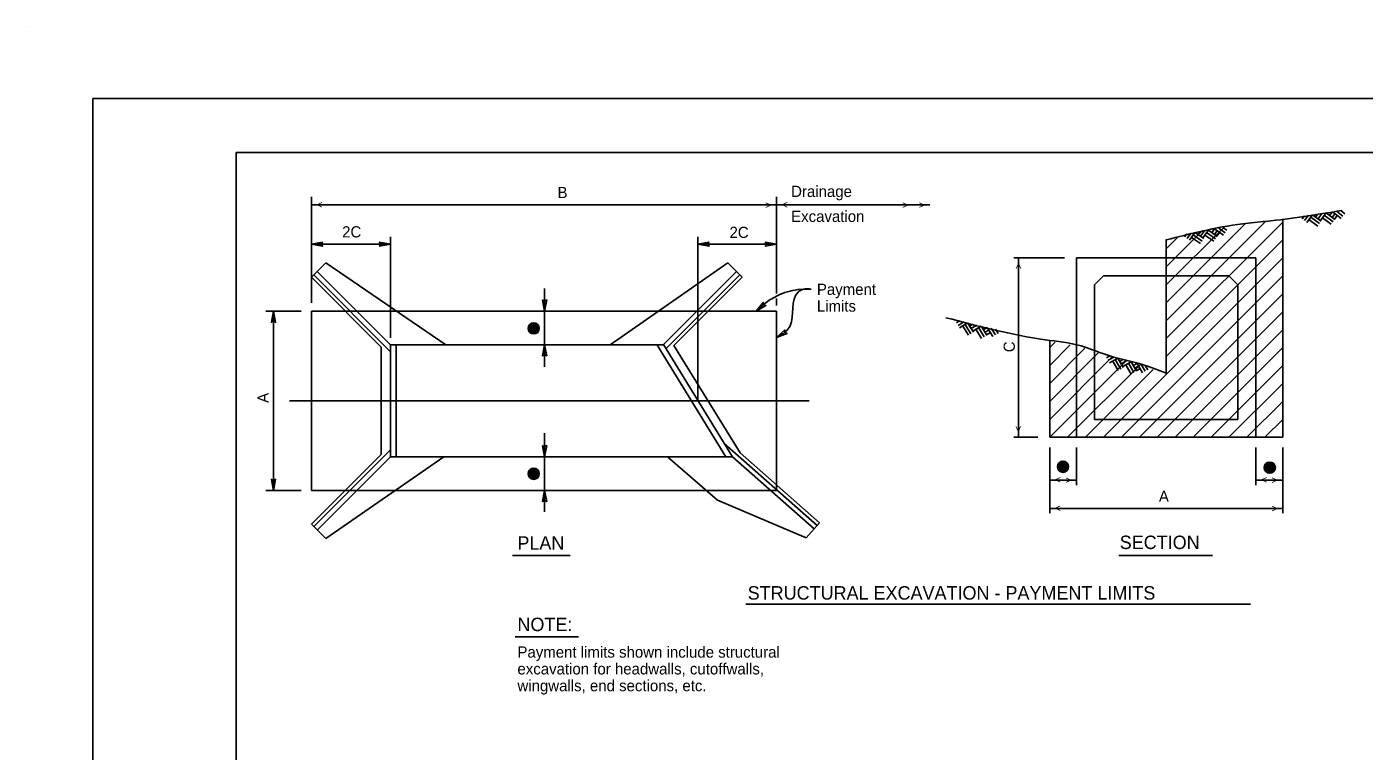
# Model space of a CAD drawing. Extents: x -0.08 to 2.83, y -0.03 to 1.92.
# Drawn here: x -0.077 to 1.477, y 1.075 to 1.917 of the extents above; entities that cross this region are included whole.
import ezdxf

# ---------------------------------------------------------------- set-up
doc = ezdxf.new("R2010")
doc.units = 0
for name, color, linetype in [('21', 7, 'Continuous'), ('50', 7, 'Continuous'), ('54', 7, 'Continuous'), ('55', 7, 'Continuous'), ('57', 7, 'Continuous'), ('63', 7, 'Continuous')]:
    doc.layers.add(name, color=color, linetype=linetype)

msp = doc.modelspace()

# ---------------------------------------------------------------- linework, layer by layer
at = {"layer": '21'}
msp.add_line((-0.0767, 1.9167), (-0.0767, 1.9167), dxfattribs=at)
at = {"layer": '50'}
for p, q in [((1.4052, 1.6937), (1.4078, 1.6971)), ((1.408, 1.6916), (1.4126, 1.6978)), ((1.4107, 1.6895), (1.4174, 1.6984)), ((1.4153, 1.6956), (1.4254, 1.688)), ((1.4174, 1.6984), (1.4275, 1.6908)), ((1.4209, 1.6958), (1.4235, 1.6992)), ((1.4237, 1.6937), (1.4283, 1.6999)), ((1.4264, 1.6916), (1.4331, 1.7005)), ((1.4289, 1.6949), (1.439, 1.6874)), ((1.431, 1.6977), (1.4411, 1.6901)), ((1.4331, 1.7005), (1.4432, 1.6929)), ((1.4372, 1.6974), (1.4404, 1.7017)), ((1.44, 1.6953), (1.4432, 1.6996)), ((1.4404, 1.7017), (1.4505, 1.6941)), ((1.4428, 1.6932), (1.446, 1.6975)), ((1.4453, 1.7024), (1.4526, 1.6968)), ((1.4501, 1.7031), (1.4547, 1.6996)), ((1.2843, 1.6754), (1.2867, 1.6789)), ((1.2871, 1.6734), (1.2916, 1.6797)), ((1.29, 1.6714), (1.2963, 1.6805)), ((1.2963, 1.6805), (1.3066, 1.6732)), ((1.3005, 1.6775), (1.3036, 1.6819)), ((1.3034, 1.6755), (1.3065, 1.6799)), ((1.3036, 1.6819), (1.3139, 1.6747)), ((1.3084, 1.6828), (1.3159, 1.6775)), ((1.3132, 1.6837), (1.3179, 1.6804)), ((1.4132, 1.6928), (1.4233, 1.6852)), ((1.2687, 1.6727), (1.2711, 1.6762)), ((1.2715, 1.6707), (1.276, 1.6771)), ((1.2744, 1.6687), (1.2807, 1.6778)), ((1.2767, 1.6721), (1.2871, 1.6649)), ((1.2787, 1.675), (1.2891, 1.6677)), ((1.2807, 1.6778), (1.291, 1.6706)), ((1.2923, 1.6748), (1.3027, 1.6676)), ((1.2943, 1.6776), (1.3047, 1.6704)), ((1.3062, 1.6735), (1.3093, 1.6779)), ((1.1432, 1.6482), (1.3515, 1.6482)), ((1.1432, 1.4399), (1.1432, 1.6482)), ((1.3515, 1.4399), (1.3515, 1.6482)), ((0.2541, 1.6257), (0.2708, 1.6424)), ((0.2609, 1.6326), (0.3461, 1.5474)), ((0.4101, 1.5474), (0.2708, 1.6424)), ((0.6012, 1.5474), (0.7379, 1.6424)), ((0.663, 1.5475), (0.7479, 1.6324)), ((0.7546, 1.6257), (0.7379, 1.6424)), ((0.2541, 1.6257), (0.3351, 1.5447)), ((0.2569, 1.6285), (0.3461, 1.5392)), ((0.6662, 1.5429), (0.7518, 1.6285)), ((0.6753, 1.5465), (0.7546, 1.6257)), ((1.164, 1.617), (1.1744, 1.6274)), ((1.164, 1.4607), (1.164, 1.617)), ((1.1744, 1.6274), (1.3202, 1.6274)), ((1.3307, 1.617), (1.3202, 1.6274)), ((1.3307, 1.4607), (1.3307, 1.617)), ((1.0036, 1.5728), (1.0072, 1.5751)), ((1.0054, 1.5698), (1.012, 1.574)), ((1.0073, 1.5669), (1.0166, 1.5728)), ((1.0137, 1.5709), (1.0204, 1.5602)), ((1.0166, 1.5728), (1.0233, 1.5621)), ((1.019, 1.5692), (1.0226, 1.5714)), ((1.0208, 1.5662), (1.0274, 1.5703)), ((1.0108, 1.5691), (1.0174, 1.5584)), ((1.0227, 1.5633), (1.0321, 1.5691)), ((1.0262, 1.5655), (1.0328, 1.5548)), ((1.0291, 1.5673), (1.0358, 1.5566)), ((1.0321, 1.5691), (1.0387, 1.5585)), ((1.0348, 1.5648), (1.0393, 1.5676)), ((1.0366, 1.5618), (1.0412, 1.5647)), ((1.0385, 1.5589), (1.043, 1.5617)), ((1.0393, 1.5676), (1.046, 1.5569)), ((1.0441, 1.5665), (1.0489, 1.5588)), ((1.0488, 1.5655), (1.0519, 1.5606)), ((0.3351, 1.4199), (0.3351, 1.5447)), ((0.3461, 1.4172), (0.3461, 1.5474)), ((0.3461, 1.5474), (0.663, 1.5474)), ((0.3526, 1.4172), (0.3526, 1.5474)), ((0.7356, 1.4174), (0.6553, 1.5475)), ((0.7433, 1.4173), (0.663, 1.5475)), ((0.7523, 1.4217), (0.6753, 1.5465)), ((1.178, 1.5323), (1.1817, 1.5344)), ((1.1798, 1.5293), (1.1865, 1.5331)), ((1.1815, 1.5263), (1.1911, 1.5318)), ((1.1851, 1.5283), (1.1914, 1.5174)), ((1.1881, 1.5301), (1.1944, 1.5191)), ((1.1911, 1.5318), (1.1974, 1.5209)), ((1.1933, 1.5281), (1.197, 1.5302)), ((1.195, 1.5251), (1.2017, 1.529)), ((1.1968, 1.5221), (1.2064, 1.5276)), ((1.2004, 1.5242), (1.2067, 1.5132)), ((1.2034, 1.5259), (1.2097, 1.515)), ((1.2064, 1.5276), (1.2127, 1.5167)), ((1.2089, 1.5232), (1.2136, 1.5258)), ((1.2136, 1.5258), (1.2199, 1.5149)), ((1.2183, 1.5246), (1.2229, 1.5167)), ((1.223, 1.5234), (1.2259, 1.5184)), ((1.2107, 1.5201), (1.2153, 1.5228)), ((1.2124, 1.5171), (1.2171, 1.5198)), ((1.164, 1.4607), (1.3307, 1.4607)), ((0.7337, 1.4328), (0.8418, 1.3376)), ((1.1432, 1.4399), (1.3515, 1.4399)), ((0.2541, 1.3389), (0.3351, 1.4199)), ((0.2569, 1.3362), (0.3461, 1.4254)), ((0.2613, 1.3324), (0.3461, 1.4172)), ((0.4078, 1.4172), (0.2708, 1.3223)), ((0.3461, 1.4172), (0.7433, 1.4172)), ((0.7258, 1.3669), (0.6679, 1.4172)), ((0.7433, 1.4173), (0.8383, 1.3336)), ((0.7523, 1.4217), (0.8445, 1.3406)), ((0.829, 1.323), (0.7258, 1.3669)), ((0.2541, 1.3389), (0.2708, 1.3223)), ((0.829, 1.323), (0.8445, 1.3406))]:
    msp.add_line(p, q, dxfattribs=at)
at = {"layer": '54'}
for points in [[(0.2541, 1.6641), (0.2671, 1.6618), (0.2656, 1.6641), (0.2669, 1.6665)], [(0.3461, 1.6641), (0.3331, 1.6665), (0.3346, 1.6641), (0.3333, 1.6617)], [(0.7032, 1.6641), (0.7162, 1.6618), (0.7147, 1.6641), (0.716, 1.6665)], [(0.7944, 1.6641), (0.7815, 1.6665), (0.783, 1.6641), (0.7816, 1.6617)], [(0.2101, 1.5865), (0.2077, 1.5735), (0.2101, 1.575), (0.2125, 1.5736)], [(0.5251, 1.5865), (0.5275, 1.5995), (0.5251, 1.598), (0.5227, 1.5993)], [(0.7707, 1.5865), (0.7822, 1.593), (0.7795, 1.5938), (0.779, 1.5965)], [(0.7944, 1.5558), (0.8068, 1.5606), (0.8042, 1.5618), (0.8042, 1.5646)], [(0.5251, 1.5474), (0.5227, 1.5344), (0.5251, 1.5359), (0.5275, 1.5346)], [(0.5251, 1.4172), (0.5275, 1.4302), (0.5251, 1.4287), (0.5227, 1.43)], [(0.2101, 1.3781), (0.2125, 1.3911), (0.2101, 1.3896), (0.2077, 1.391)], [(0.5251, 1.3781), (0.5227, 1.3652), (0.5251, 1.3667), (0.5275, 1.3653)]]:
    msp.add_lwpolyline(points, close=True, dxfattribs=at)
at = {"layer": '55'}
for p, q in [((0.2541, 1.5962), (0.2541, 1.7192)), ((0.2541, 1.7098), (0.7944, 1.7098)), ((0.7944, 1.6069), (0.7944, 1.7192)), ((0.7944, 1.7098), (0.9728, 1.7098)), ((1.2473, 1.5753), (1.3623, 1.6903)), ((1.2473, 1.5545), (1.3827, 1.6899)), ((1.2473, 1.5961), (1.3393, 1.6881)), ((1.2473, 1.617), (1.3153, 1.6849)), ((1.2473, 1.6378), (1.2896, 1.6801)), ((1.3827, 1.4399), (1.3827, 1.6935)), ((0.2541, 1.6641), (0.3461, 1.6641)), ((0.3461, 1.5555), (0.3461, 1.6729)), ((0.7032, 1.4824), (0.7032, 1.6729)), ((0.7032, 1.6641), (0.7944, 1.6641)), ((1.2473, 1.6586), (1.2613, 1.6726)), ((1.2473, 1.5137), (1.2473, 1.6697)), ((1.2473, 1.5336), (1.3827, 1.6691)), ((1.0702, 1.6482), (1.1292, 1.6482)), ((1.0755, 1.4401), (1.0755, 1.6482)), ((1.1744, 1.4399), (1.3827, 1.6482)), ((1.1952, 1.4399), (1.3827, 1.6274)), ((0.5251, 1.5865), (0.5251, 1.6126)), ((0.7944, 1.5928), (0.7944, 1.6011)), ((1.2161, 1.4399), (1.3827, 1.6066)), ((0.2011, 1.5865), (0.2421, 1.5865)), ((0.2101, 1.3781), (0.2101, 1.5865)), ((0.2541, 1.3781), (0.2541, 1.5865)), ((0.2541, 1.5865), (0.7944, 1.5865)), ((0.5251, 1.5474), (0.5251, 1.5865)), ((0.7944, 1.3781), (0.7944, 1.5865)), ((1.2369, 1.4399), (1.3827, 1.5857)), ((1.2577, 1.4399), (1.3827, 1.5649)), ((0.5251, 1.5219), (0.5251, 1.5474)), ((1.1119, 1.4399), (1.1119, 1.5521)), ((1.1119, 1.5441), (1.1181, 1.5502)), ((1.1119, 1.5232), (1.1358, 1.5471)), ((1.1119, 1.5024), (1.1529, 1.5434)), ((1.2786, 1.4399), (1.3827, 1.5441)), ((1.1119, 1.4816), (1.1683, 1.538)), ((1.1119, 1.4607), (1.1842, 1.533)), ((1.1119, 1.4399), (1.2006, 1.5286)), ((1.1327, 1.4399), (1.2169, 1.524)), ((1.2994, 1.4399), (1.3827, 1.5232)), ((1.1536, 1.4399), (1.2323, 1.5186)), ((1.3202, 1.4399), (1.3827, 1.5024)), ((0.2287, 1.4823), (0.8326, 1.4823)), ((1.3411, 1.4399), (1.3827, 1.4816)), ((1.3619, 1.4399), (1.3827, 1.4607)), ((0.5251, 1.4172), (0.5251, 1.4446)), ((1.0702, 1.4399), (1.0982, 1.4399)), ((1.1119, 1.4399), (1.1432, 1.4399)), ((1.3515, 1.4399), (1.3827, 1.4399)), ((0.5251, 1.3781), (0.5251, 1.4172)), ((1.1119, 1.3518), (1.1119, 1.428)), ((1.1432, 1.3843), (1.1432, 1.428)), ((1.3515, 1.3843), (1.3515, 1.428)), ((1.3827, 1.3518), (1.3827, 1.428)), ((1.1119, 1.3903), (1.1432, 1.3903)), ((1.3515, 1.3903), (1.3827, 1.3903)), ((0.2011, 1.3781), (0.2421, 1.3781)), ((0.2541, 1.3781), (0.7944, 1.3781)), ((0.5251, 1.3532), (0.5251, 1.3781)), ((1.1119, 1.3574), (1.3827, 1.3574))]:
    msp.add_line(p, q, dxfattribs=at)
for points in [[(1.2473, 1.6692), (1.2889, 1.6793), (1.3362, 1.6879), (1.3635, 1.6907), (1.4513, 1.7033)], [(0.8346, 1.6119), (0.8253, 1.6119), (0.8014, 1.6069), (0.7841, 1.5976), (0.7707, 1.5865)], [(0.8346, 1.6119), (0.8258, 1.6119), (0.8195, 1.6084), (0.8102, 1.5694), (0.8049, 1.5626), (0.7944, 1.5558)], [(1.2473, 1.5144), (1.2144, 1.5259), (1.1771, 1.5359), (1.1484, 1.546), (1.1068, 1.5532), (0.9914, 1.5788)]]:
    msp.add_spline(points, degree=3, dxfattribs=at)
at = {"layer": '57'}
for p, q in [((0.5124, 1.5599), (0.5124, 1.5729)), ((0.5124, 1.3909), (0.5124, 1.404)), ((1.1209, 1.4057), (1.1339, 1.4057)), ((1.3611, 1.4047), (1.3741, 1.4047)), ((0.4879, 1.3026), (0.5548, 1.3026)), ((1.1921, 1.3026), (1.3011, 1.3026)), ((0.7588, 1.2462), (1.3452, 1.2462)), ((0.4909, 1.2081), (0.5644, 1.2081))]:
    msp.add_line(p, q, dxfattribs=at)
for points in [[(0.5065, 1.5673), (0.507, 1.5642), (0.5072, 1.5693), (0.5076, 1.5627), (0.5079, 1.5703), (0.5083, 1.5623), (0.5089, 1.5713), (0.5089, 1.5613), (0.51, 1.572), (0.51, 1.5608), (0.5108, 1.5724), (0.5107, 1.5604), (0.5115, 1.5725), (0.5116, 1.5603), (0.512, 1.5727)], [(0.5184, 1.5656), (0.5179, 1.5687), (0.5177, 1.5636), (0.5173, 1.5702), (0.5169, 1.5625), (0.5166, 1.5706), (0.516, 1.5616), (0.5159, 1.5716), (0.5149, 1.5609), (0.5149, 1.5721), (0.514, 1.5605), (0.5142, 1.5725), (0.5133, 1.5604), (0.5133, 1.5725), (0.5129, 1.5602)], [(0.5065, 1.3983), (0.507, 1.3952), (0.5072, 1.4004), (0.5076, 1.3937), (0.5079, 1.4014), (0.5083, 1.3933), (0.5089, 1.4023), (0.5089, 1.3923), (0.51, 1.403), (0.51, 1.3918), (0.5108, 1.4034), (0.5107, 1.3914), (0.5115, 1.4036), (0.5116, 1.3914), (0.512, 1.4037)], [(0.5184, 1.3966), (0.5179, 1.3998), (0.5177, 1.3946), (0.5173, 1.4013), (0.5169, 1.3936), (0.5166, 1.4017), (0.516, 1.3926), (0.5159, 1.4026), (0.5149, 1.3919), (0.5149, 1.4032), (0.514, 1.3915), (0.5142, 1.4035), (0.5133, 1.3914), (0.5133, 1.4036), (0.5129, 1.3913)], [(1.1283, 1.4116), (1.1252, 1.4111), (1.1303, 1.4109), (1.1237, 1.4105), (1.1313, 1.4101), (1.1233, 1.4098), (1.1323, 1.4092), (1.1223, 1.4091), (1.133, 1.4081), (1.1218, 1.4081), (1.1334, 1.4072), (1.1214, 1.4074), (1.1335, 1.4065), (1.1213, 1.4065), (1.1337, 1.4061)], [(1.1283, 1.3998), (1.1252, 1.4002), (1.1303, 1.4004), (1.1237, 1.4008), (1.1313, 1.4012), (1.1233, 1.4015), (1.1323, 1.4021), (1.1223, 1.4022), (1.133, 1.4032), (1.1218, 1.4032), (1.1334, 1.4041), (1.1214, 1.404), (1.1335, 1.4048), (1.1213, 1.4049), (1.1337, 1.4053)], [(1.3685, 1.4106), (1.3654, 1.4101), (1.3705, 1.4099), (1.3639, 1.4095), (1.3715, 1.4092), (1.3635, 1.4088), (1.3725, 1.4082), (1.3625, 1.4082), (1.3732, 1.4071), (1.362, 1.4071), (1.3736, 1.4063), (1.3616, 1.4064), (1.3737, 1.4056), (1.3615, 1.4055), (1.3739, 1.4051)], [(1.3685, 1.3988), (1.3654, 1.3993), (1.3705, 1.3995), (1.3639, 1.3999), (1.3715, 1.4002), (1.3635, 1.4006), (1.3725, 1.4012), (1.3625, 1.4012), (1.3732, 1.4023), (1.362, 1.4023), (1.3736, 1.4031), (1.3616, 1.403), (1.3737, 1.4038), (1.3615, 1.4039), (1.3739, 1.4043)]]:
    msp.add_lwpolyline(points, dxfattribs=at)
for centre in [(0.5124, 1.5664), (0.5124, 1.3975), (1.1274, 1.4057), (1.3676, 1.4047)]:
    msp.add_circle(centre, 0.00651, dxfattribs=at)
at = {"layer": '63'}
for p, q in [((0, 1.8333), (2.8333, 1.8333)), ((0, 0), (0, 1.8333)), ((0.0033, 1.833), (0.0033, 1.833)), ((1.1958, 1.4469), (1.1958, 1.4469))]:
    msp.add_line(p, q, dxfattribs=at)
msp.add_lwpolyline([(0.1667, 0.0624), (0.1667, 1.7708), (2.7292, 1.7708), (2.7292, 0.1041), (2.5625, 0.1041), (2.5625, 0.1458), (2.0739, 0.1458), (2.0739, 0.0624)], close=True, dxfattribs=at)

# ---------------------------------------------------------------- texts
at = {"layer": '55'}
for rotation, p in [(180, (0.2671, 1.7141)), (180, (0.8075, 1.7141)), (90, (1.0798, 1.6352)), (270, (1.0712, 1.4532)), (180, (1.1249, 1.3947)), (180, (1.3645, 1.3947)), (180, (1.1249, 1.3617))]:
    msp.add_text('>', height=0.00868, rotation=rotation, dxfattribs=at).set_placement(p)
for p in [(0.7814, 1.7054), (0.9405, 1.7054), (0.9597, 1.7054), (1.1301, 1.386), (1.1301, 1.386), (1.3697, 1.386), (1.3697, 1.353)]:
    msp.add_text('>', height=0.00868, dxfattribs=at).set_placement(p)
at = {"layer": '57'}
for s, height, p in [('B', 0.013, (0.5401, 1.7177)), ('Drainage', 0.01302, (0.8115, 1.719)), ('Excavation', 0.01302, (0.8115, 1.69)), ('2C', 0.01302, (0.2898, 1.672)), ('2C', 0.01302, (0.7399, 1.6714)), ('Payment', 0.01302, (0.8414, 1.6053)), ('Limits', 0.01302, (0.8414, 1.5858)), ('A', 0.013, (1.2388, 1.365)), ('PLAN', 0.01562, (0.4934, 1.3093)), ('SECTION', 0.01562, (1.1933, 1.3101)), ('STRUCTURAL EXCAVATION - PAYMENT LIMITS ', 0.015625, (0.761, 1.2514)), ('NOTE:', 0.01562, (0.4935, 1.2148)), ('Payment limits shown include structural', 0.013021, (0.4935, 1.184)), ('excavation for headwalls, cutoffwalls,', 0.013021, (0.4935, 1.1645)), ('wingwalls, end sections, etc.', 0.013021, (0.4935, 1.145))]:
    msp.add_text(s, height=height, dxfattribs=at).set_placement(p)
for s, p in [('C', (1.0714, 1.5387)), ('A', (0.2043, 1.4799))]:
    msp.add_text(s, height=0.013, rotation=90, dxfattribs=at).set_placement(p)

doc.saveas('drawing.dxf')
